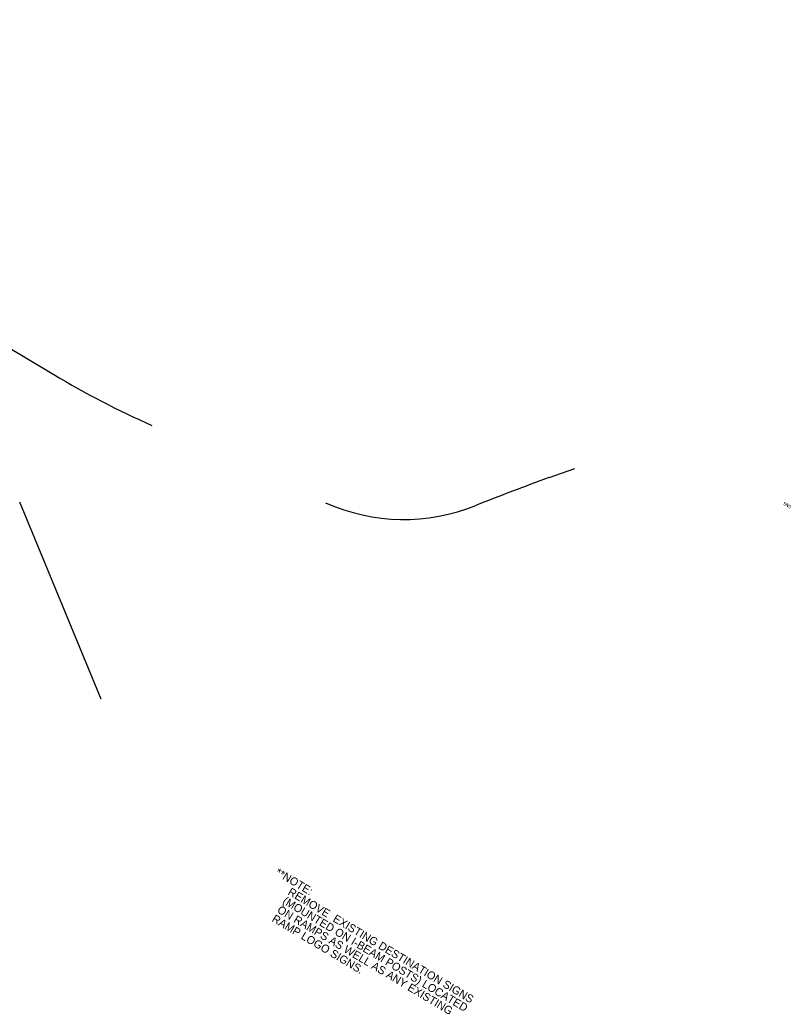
# Model space of a CAD drawing. Extents: x 2344331 to 2350764, y 366700 to 371189.
# Drawn here: x 2348357 to 2350764, y 366700 to 369805 of the extents above; entities that cross this region are included whole.
import ezdxf

# ---------------------------------------------------------------- set-up
doc = ezdxf.new("R2010")
doc.units = 0
for name, color, linetype in [('RD_HC_Cl', 7, 'Continuous'), ('RD_PD_Final_LnLine', 7, 'Continuous'), ('RD_SHT_TX', 7, 'Continuous'), ('TR SN UNASSIGNED 2', 7, 'Continuous')]:
    doc.layers.add(name, color=color, linetype=linetype)

msp = doc.modelspace()

# ---------------------------------------------------------------- linework, layer by layer
at = {"layer": 'RD_HC_Cl'}
for p, q in [((2346606.5, 369804.5), (2348463.1, 368696.8)), ((2346606.5, 369804.5), (2348463.1, 368696.8)), ((2346606.5, 369804.5), (2348463.1, 368696.8)), ((2346606.5, 369804.5), (2348463.1, 368696.8)), ((2350009.4, 368375.2), (2350089.1, 368403.6)), ((2350009.4, 368375.2), (2350089.1, 368403.6)), ((2350009.4, 368375.2), (2350089.1, 368403.6)), ((2350009.4, 368375.2), (2350089.1, 368403.6))]:
    msp.add_line(p, q, dxfattribs=at)
for centre, radius, start, end in [((2349949, 371187.2), 2900, 239.1785, 245.9774), ((2349949, 371187.2), 2900, 239.1785, 245.9774), ((2349949, 371187.2), 2900, 239.1785, 245.9774), ((2349949, 371187.2), 2900, 239.1785, 245.9774), ((2351947.8, 362927.7), 5782.1, 109.58804, 112.01473), ((2351947.8, 362927.7), 5782.1, 109.58804, 112.01473), ((2351947.8, 362927.7), 5782.1, 109.58804, 112.01473), ((2351947.8, 362927.7), 5782.1, 109.58804, 112.01473), ((2349555.5, 368844.5), 600, 245.9774, 292.0147), ((2349555.5, 368844.5), 600, 245.9774, 292.0147), ((2349555.5, 368844.5), 600, 245.9774, 292.0147), ((2349555.5, 368844.5), 600, 245.9774, 292.0147)]:
    msp.add_arc(centre, radius, start, end, dxfattribs=at)
at = {"layer": 'RD_PD_Final_LnLine'}
msp.add_line((2348611, 367683.9), (2348357, 368298.5), dxfattribs=at)
msp.add_line((2348611, 367683.9), (2348357, 368298.5), dxfattribs=at)
msp.add_line((2348611, 367683.9), (2348357, 368298.5), dxfattribs=at)
msp.add_line((2348611, 367683.9), (2348357, 368298.5), dxfattribs=at)

# ---------------------------------------------------------------- texts
at = {"layer": 'RD_SHT_TX'}
msp.add_text('SN5', height=10, rotation=329.1785, dxfattribs=at).set_placement((2350737.8, 368291.9))
at = {"layer": 'TR SN UNASSIGNED 2'}
for s, p in [('**NOTE:', (2349152.1, 367136)), ('       REMOVE  EXISTING DESTINATION SIGNS', (2349135.4, 367108.1)), ('       (MOUNTED ON I-BEAM POSTS) LOCATED', (2349118.8, 367080.1)), ('       ON RAMPS AS WELL AS ANY EXISTING', (2349102.1, 367052.2)), ('       RAMP LOGO SIGNS.', (2349085.4, 367024.2))]:
    msp.add_text(s, height=25, rotation=329.1785, dxfattribs=at).set_placement(p)

doc.saveas('drawing.dxf')
